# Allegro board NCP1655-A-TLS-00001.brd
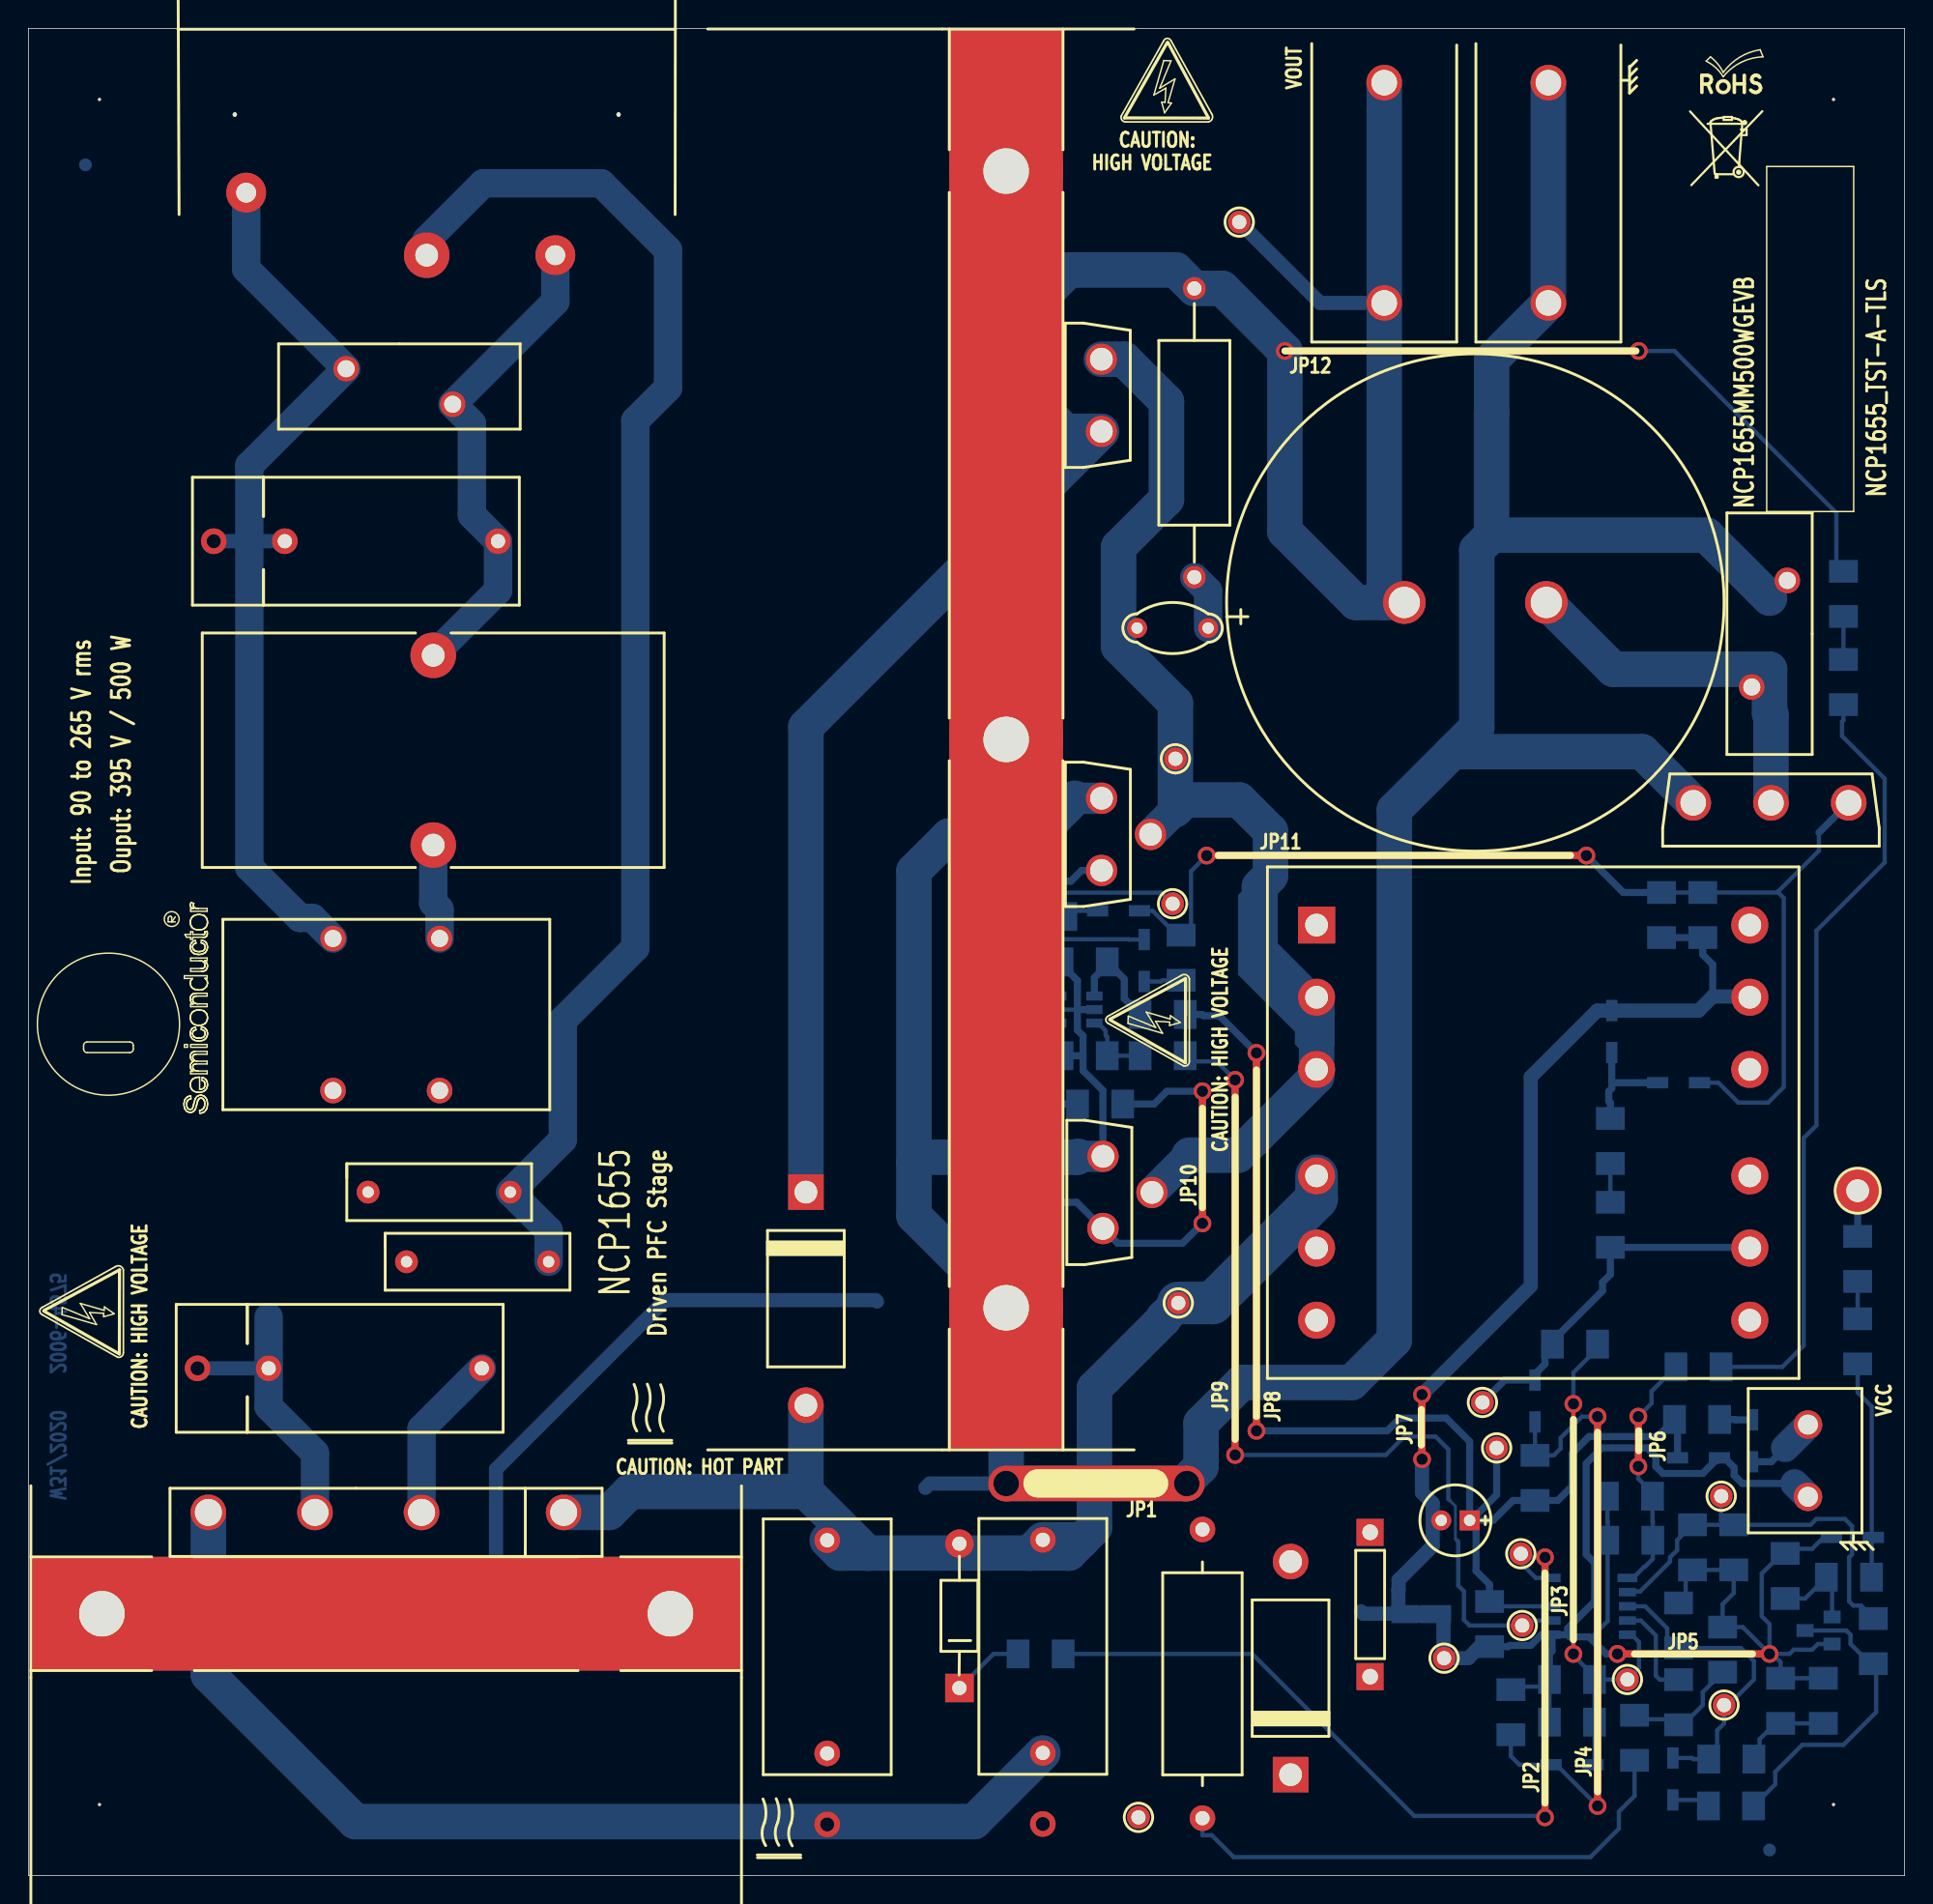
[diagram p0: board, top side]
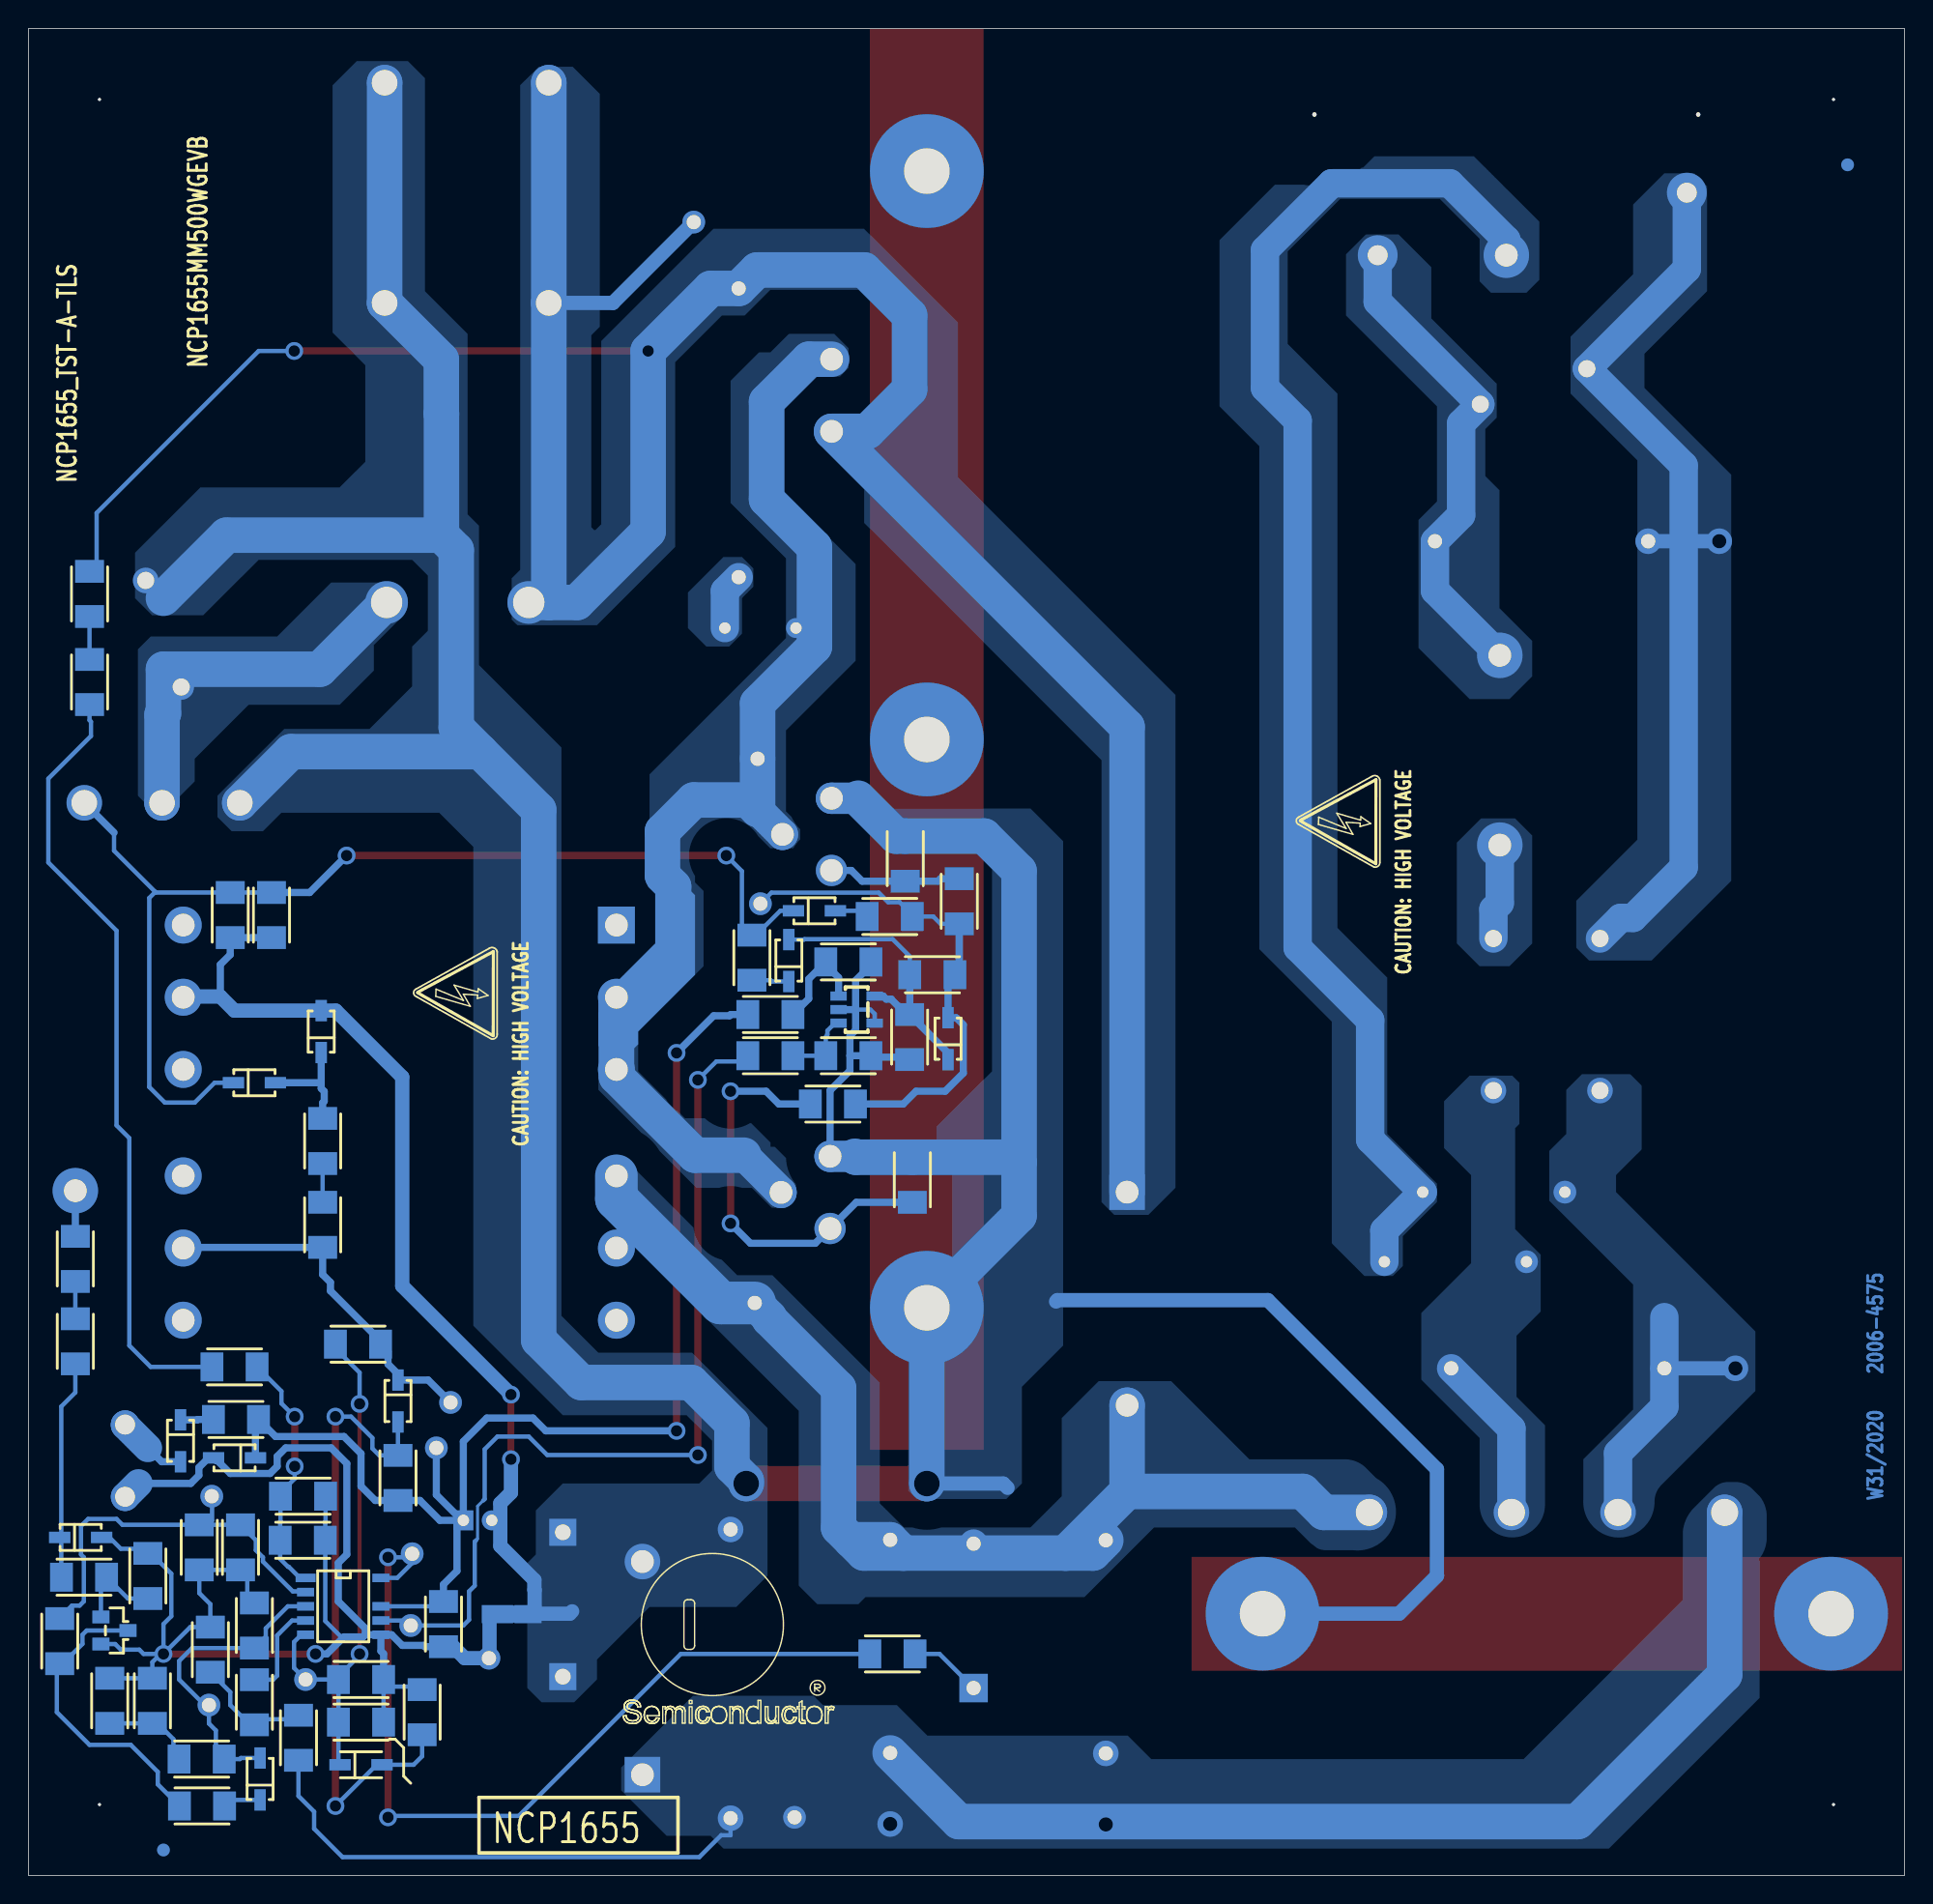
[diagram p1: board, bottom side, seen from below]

Outline 132 x 130 mm; copper layers: TOP, IN1, IN2, BOTTOM. Coordinates in mm from the lower left corner of the outline.
Outline path: 0,130 0,0 132,0 132,130 0,130

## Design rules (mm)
net group DRV: nets CS DRV FB GND N12561389 N12563930 N12564274 N12565260 N12565696 N12574373 N12574975 N12575513 N12577351 N12577403 N12578828 N12578907 N12579145 N12580736 N12597521 N125743211 PFCOK SKIP_CONTROL2 VAUX VCC VM ZCD
net group V_HT: nets VHV

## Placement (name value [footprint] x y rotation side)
C1  470nF/X2  [CAP_E9_L18_H17V5_P15_P20]  25.54 93.91 0 top
C2  470nF/X2  [CAP_E9_L18_H17V5_P15_P20]  24.4 35.7 0 top
C3A  680nF/X2  [CAP_E9_L18_H17V5_P15]  71.37 16.13 270 top
C3B  680nF/X2  [CAP_E9_L18_H17V5_P15]  56.2 16.1 270 top
C4  330uF/450V  [CAPA_CH_D35_H42_P10]  101.8 89.6 0 top
C5  1nF/Y  [CAP_E4_L13_H9_P10]  31.6 43.2 180 top
C6  1nF/Y  [CAP_E4_L13_H9_P10]  28.9 48.1 180 top
C7  220pF  [1206]  74.31 57.7 180 bottom
C8  470nF  [1206]  74.31 64.3 180 bottom
C9  100pF  [CAP_DISK_D5_E3V5_P5]  80.5 87.8 180 top
C10  220pF  [1206]  70 59.01 270 bottom
C11  10nF  [1206]  111.3 51.7 90 bottom
C12  2.2nF  [1206]  117.8 67.6 270 bottom
C14  2.2nF  [1206]  112.7 23.6 180 bottom
C15  10nF  [1206]  119.98 23.1 270 bottom
C16  220pF  [1206]  119.2 15.9 90 bottom
C17  2.2nF  [1206]  116.1 17.6 90 bottom
C18  10nF  [1206]  123.28 12.3 90 bottom
C19  47uF  [CAPA_CH_D5_H11_P2]  100.4 25 180 top
C20  22nF  [1206]  128.7 37.6 270 bottom
C21  22pF  [1206]  104.3 11.5 90 bottom
C22  220nF  [1206]  102.8 17.7 270 bottom
C23  22pF  [1206]  108.6 13.8 180 bottom
CB3  target_cms  [MIRE_LOW]  4.01 120.4 180 bottom
CB4  target_cms  [MIRE_LOW]  122.5 1.8 180 bottom
CM1  2x2mH  [SELF_WE-CMB_M]  25.18 60.6 90 top
D1  FFSPF0865A  [TO220_2P]  75.49 104.18 90 top
D2  1N5406  [DO201AD]  54.7 40.6 270 top
D3  1N5406  [DO201AD]  88.8 14.6 90 top
D4  1N4148  [SOD123]  76.7 67.9 180 bottom
D5  1N4148  [SOD123]  67.3 58.9 90 bottom
D7  1N4148  [SOD123]  116.1 55.8 180 bottom
D8  1N4148  [SOD123]  78.5 64.4 90 bottom
D10  1N4007  [DO41]  65.5 18.28 90 top
D11  1N4148  [SOD123]  106 33.4 270 bottom
D12  1N4148  [SOD123]  115.7 6.8 90 bottom
D13  1N4148  [SOD123]  121.3 30.6 270 bottom
D14  1N4148  [SOD123]  108.6 7.8 180 bottom
DRV  -  [TP]  105.1 17.6 0 top
DZ1  MMSZ18T1  [SOD123]  111.4 59.4 90 bottom
DZ3  MMSZ18T1  [SOD123]  128.32 23.8 180 bottom
DZ4  MMSZ18T1  [SOD123]  117.5 29.4 0 bottom
GND  -  [TP]  99.6 15.3 0 top
HS1  SK481-50  [DISIPATEUR_SK481-50]  25.17 18.43 0 top
HS2  SK481-100  [DISIPATEUR_SK481-100]  68.79 79.96 270 top
ISENSE  -  [TP]  78.1 4.1 0 top
J1  CC_copper  [NONE_CUST]  97.7 18.4 0 bottom
J1A  24.243.2  [CONN_BANANE-4MM_H]  106.94 118.43 90 top
J1B  24.243.1  [CONN_BANANE-4MM_H]  95.39 118.43 90 top
J10  con_3p_1fuse  [CON_SCHUTER_GSF1-1201-31]  28.02 114.04 180 top
J11  HEADER 2  [CON_BORNIER_2_P508]  125.2 29.2 270 top
JGND  STRAP GND  [JUMPER400H]  94.4 14 90 top
L1  175uH  [WE_INDUCTOR_PWD]  105.87 52.99 0 top
L2  56uH  [SELF_2310-V-RC]  28.48 79.2 270 top
NOREF  -  []  5 125 90 top
NOREF#2  -  []  0 130 0 top
NOREF#3  -  []  129.7 123.1 0 top
NOREF#4  -  []  -71.8 6.6 0 top
NOREF#5  -  []  96.1 16.7 0 top
NOREF#6  -  [unnamed#2]  5 125 0 top
NOREF#7  -  [unnamed#2]  127 125 0 top
NOREF#8  -  [unnamed#2]  5 5 0 top
NOREF#9  -  []  0 130 0 top
NOREF#10  -  [unnamed#2]  127 5 0 top
NOREF#11  -  []  -177.26 -15.11 0 top
NOREF#12  -  []  0 0 90 top
NOREF#13  -  []  198 -3.3 180 bottom
NTC1  B57237S0100M0  [DISK_D17_E6_P7-5]  122.5 87.4 270 top
PFCOK  -  [TP]  119.1 26.7 0 top
Q1A  FCFP165N65  [TO220]  75.5 73.28 90 top
Q1B  FCFP165N65  [TO220]  75.6 48.08 90 top
Q2  FCA76N60  [TO247]  122.6 75.5 180 top
Q6  MMBT489LT1  [SOT23]  125.95 17.25 90 bottom
R1  47R  [1206]  111.3 45.8 270 bottom
R2  4.7R  [1206]  81.1 64.6 270 bottom
R3  0R  [RES_1W_AC01]  82.03 101.54 90 top
R4  4.7R  [1206]  68.4 63.4 180 bottom
R5  47R  [1206]  79.8 60.6 180 bottom
R8  4.7R  [1206]  66.51 68.57 270 bottom
R9  4.7R  [1206]  75.4 54.3 180 bottom
R10  27K  [1206]  108.81 37.4 180 bottom
R11  27K  [1206]  70.31 71.57 270 bottom
R12  27K  [1206]  69.81 48.97 270 bottom
R13  27K  [1206]  114.9 67.6 90 bottom
R14  0.03/3W  [RES_LVR03]  82.6 14.2 90 top
R15  47R  [1206]  79.8 57.7 180 bottom
R16  4.7R  [1206]  71.4 67.5 0 bottom
R17  27K  [1206]  71.21 15.6 180 bottom
R18  27K  [1206]  106 27.99 90 bottom
R20  470R  [1206]  129.8 16.5 90 bottom
R21  560k  [1206]  127.7 90.2 270 bottom
R22  1.8M  [1206]  127.7 84 270 bottom
R23  1.8M  [1206]  117.5 35.8 180 bottom
R24  27K  [1206]  112.68 26.7 180 bottom
R25  56K  [1206]  117.08 23.1 90 bottom
R26  1K  [1206]  113 9.7 90 bottom
R27  1K  [1206]  116.1 12.2 90 bottom
R28  1K  [1206]  119.81 8.2 180 bottom
R29  10k  [1206]  126.28 12.3 90 bottom
R30  10k  [1206]  108.6 10.8 0 bottom
R31  47R  [1206]  117.4 32.1 0 bottom
R32  470R  [1206]  119.79 4.9 0 bottom
R33  47R  [1206]  128.7 43.4 270 bottom
R34  10k  [1206]  128.09 21 0 bottom
R35  10k  [1206]  123.6 21.09 90 bottom
SKIP_CTRL2  TP  [TP_T2]  128.7 48.2 0 top
U1  GS1B1580  [PONT_RD_GSI-5S]  25.16 25.56 0 top
U2  NCP1655  [SO10_-1_1MM]  109.85 18.95 180 bottom
U3  FAN3100tsx  [SOT23-5]  73.73 60.95 270 bottom
V1  820513011  [DISK_D17_E6_P7-5]  26.1 104.8 0 top
VAUX  -  [TP]  102.3 33.3 270 top
VCC  -  [TP]  103.3 30.1 270 top
VDS  -  [TP]  80.7 78.6 90 top
VGATE  -  [TP]  80.5 68.4 90 top
VHV  -  [TP]  105 22.65 0 top
VIN  -  [TP]  80.9 40.3 90 top
VM  -  [TP]  119.3 12 0 top
VOUT  -  [TP]  85.19 116.37 0 top
ZCD  -  [TP]  112.5 13.8 0 top

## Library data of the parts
C1 C2 C3A C3B C5-C12 C14-C18 C20-C23 = C
C4 = CAP POL
C19 = C_elect_0
CB3 CB4 = target_cms
CM1 = WE-CMB_0
D1 D4 D5 D7 D8 D10-D14 = MMSD4148T1_0
D2 D3 = D1N4937_1
DRV GND ISENSE PFCOK VAUX VCC VDS VGATE VHV VIN VM VOUT ZCD = SLB4-I/90_0
DZ1 DZ3 DZ4 = zener_sot23_0
HS1 HS2 = Heatsink_KL_196
J1 = CC_cooper
J1A J1B = HEADER 1_1
J10 = con_3p_1fuse
J11 = HEADER 2
JGND = STRAP GND_0
L1 = WE-CMB_1
L2 = L_1
NTC1 = VARISTOR
Q1A Q1B Q2 = SPP11N60S5
Q6 = MMBT2222AL
R1-R5 R8-R18 R20-R35 = R
SKIP_CTRL2 = TEST POINT
U1 = KBUxK_1
U2 = NCL3008x_sup_0
U3 = FAN3100tsx
V1 = VARISTOR SYM

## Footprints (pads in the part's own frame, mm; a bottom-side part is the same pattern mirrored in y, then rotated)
1206
  rect 1.6x2.03 smd: 1(-1.587,0) 2(1.587,0)
CAP_DISK_D5_E3V5_P5
  round 1.4 hole 0.8: 1(-2.5,0) 2(2.5,0)
CAP_E4_L13_H9_P10
  round 1.6 hole 0.8: 1(-5,0) 2(5,0)
CAP_E9_L18_H17V5_P15
  round 1.8 hole 1: 1(7.5,0) 2(-7.5,0)
CAP_E9_L18_H17V5_P15_P20
  round 1.8 hole 1: 1(7.5,0) 2(-7.5,0)
CAPA_CH_D5_H11_P2
  rect 1.4x1.4 hole 0.8: 1(-1,0)
  round 1.4 hole 0.8: 2(1,0)
CAPA_CH_D35_H42_P10
  round 3 hole 2.2: 1(-5,0) 2(5,0)
CON_BORNIER_2_P508
  round 2 hole 1.4: 1(-2.54,0) 2(2.54,0)
CON_SCHUTER_GSF1-1201-31
  round 0.3 hole 6 unplated: (-13.5,-9.9) (13.5,-9.9)
  round 2.8 hole 1.4: 1(12.7,-4.399) 3(-9.05,0)
  round 3.2 hole 1.6: 2(0,0)
CONN_BANANE-4MM_H
  round 2.5 hole 1.8: 1(-7.75,0) 2(7.75,0)
DISIPATEUR_SK481-50
  round 8 hole 3.2: 1(-20,0) 2(20,0)
DISIPATEUR_SK481-100
  round 8 hole 3.2: (0,0) 1(-40,0) 2(40,0)
DISK_D17_E6_P7-5
  round 1.8 hole 1.2: 1(-3.75,1.25) 2(3.75,-1.25)
DO41
  rect 2x2 hole 1: 1(-5.08,0)
  round 2 hole 1: 2(5.08,0)
DO201AD
  rect 2.5x2.5 hole 1.6: 1(-7.5,0)
  round 2.5 hole 1.6: 2(7.5,0)
JUMPER400H
  rect 1.9x1.9 hole 1.1: 1(0,0) 2(10.16,0)
MIRE_LOW
  round 0.9 smd: 1(0,0)
NONE_CUST
  round 0.3 smd: 1(0,0) 2(0.318,0)
PONT_RD_GSI-5S
  round 2.5 hole 1.9: 1(12.5,0) 2(2.5,0) 3(-5,0) 4(-12.5,0)
RES_1W_AC01
  round 1.6 hole 1: 1(-10.16,0) 2(10.16,0)
RES_LVR03
  round 1.8 hole 1: 1(-10.16,0) 2(10.16,0)
SELF_2310-V-RC
  round 3.2 hole 1.6: 1(-6.678,0) 2(6.678,0)
SELF_WE-CMB_M
  round 1.8 hole 1.2: 1(-5.35,3.75) 2(5.35,3.75) 3(5.35,-3.75) 4(-5.35,-3.75)
SO10_-1_1MM
  rect 1.4x0.6 smd: 1(-2.65,2)
  rect 1.2x0.6 smd: 2(-2.65,1) 3(-2.65,0) 4(-2.65,-1) 5(-2.65,-2) 6(2.65,-2) 7(2.65,-1) 8(2.65,0) 10(2.65,2)
SOD123
  rect 1.5x0.8 smd: 1(-1.475,0) 2(1.475,0)
SOT23
  rect 0.9x1.2 smd: 1(0.953,0.953) 2(-0.953,0.953) 3(0,-0.953)
SOT23-5
  rect 0.64x1.15 smd: 1(-0.953,-1.27) 2(0,-1.27) 3(0.953,-1.27) 4(0.953,1.27) 5(-0.953,1.27)
TO220
  round 2.2 hole 1.6: 1(-2.54,0) 2(0,-3.45) 3(2.54,0)
TO220_2P
  round 2.2 hole 1.6: 1(-2.54,0) 2(2.54,0)
TO247
  round 2.5 hole 1.8: 1(-5.47,0) 2(0,0) 3(5.47,0)
TP
  round 1.6 hole 1: 1(0,0)
TP_T2
  round 3.2 hole 1.6: 1(0,0)
unnamed#2
  round 0.2 hole 3 unplated: (0,0)
WE_INDUCTOR_PWD
  rect 2.6x2.6 hole 1.6: (-15.24,13.905)
  round 2.6 hole 1.6: (-15.24,8.825) (-15.24,-8.825) (-15.24,-13.905) (15.24,13.905) (15.24,3.745) (15.24,-3.745) (15.24,-13.905) 3(-15.24,3.745) 4(-15.24,-3.745) 8(15.24,-8.825) 11(15.24,8.825)

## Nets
GND: C14.2 C15.2 C16.2 C17.2 C18.2 C21.2 C22.2 C23.2 DZ3.2(ANODE) DZ4.2(ANODE) GND.1 J1.2 J11.2 Q6.2(EMITTER) R24.2 R25.1 R29.2 R30.1 R35.2 U2.6
PGND: C7.2 C8.2 C10.2 C12.2 C19.2(-) D3.2 DZ1.2(ANODE) HS1.2 HS2.2 J1.1 J1A.1 J1A.2 JGND.1 JGND.2 L1.11 NTC1.1 Q1A.3(S) Q1B.3(S) Q2.3(S) R11.1 R12.1 R13.1 R14.2 U3.2(GND) U3.4(IN-)
VCC: C19.1(+) C22.1 DZ4.1(CATHODE) R5.1 R18.1 R31.1 U2.8 VCC.1
VIN: C3A.2 C3B.2 D2.2 D10.2(A) L1.4 U1.1(+) VIN.1
CS: R27.2 U2.4
DRV: DRV.1 R15.1 U2.7
FB: C14.1 R23.2 R24.1 U2.1
ISENSE: C3A.1 C3B.1 D3.1 ISENSE.1 R14.1 R26.1 U1.4(-)
PFCOK: C15.1 PFCOK.1 R20.2 R25.2 U2.2
SKIP_CONTROL2: R33.1 SKIP_CTRL2.1
VAUX: D11.1(C) L1.8 R1.2 R10.2 VAUX.1
VDS: C9.2 D1.2(A) L1.3 Q1A.2(D) Q1B.2(D) VDS.1
VGATE: D5.2(A) R4.2 R8.2 R9.2 R16.1 VGATE.1
VHV: R17.1 U2.10 VHV.1
VM: C17.1 D12.2(A) R28.2 U2.3 VM.1
VOUT: C4.1 D1.1(C) D2.1 J1B.1 J1B.2 R3.2 R21.1 VOUT.1
ZCD: C23.1 D14.1(C) R10.1 R30.2 U2.5 ZCD.1
N12553072: C1.1 J10.3 L2.1 V1.2
N12553076: C1.2 CM1.2 J10.1 V1.1
N12553080: C5.1 C6.1 J10.2
N12553128: CM1.3 L2.2
N12553139: C2.2 C6.2 CM1.1 U1.3(AC2)
N12553193: C2.1 C5.2 CM1.4 U1.2(AC1)
N12561389: C11.1 R1.1
N12563930: C7.1 R15.2 U3.3(IN+)
N12564274: Q1A.1(G) R8.1 R11.2
N12565260: Q1B.1(G) R9.1 R12.2
N12565625: C4.2 NTC1.2 Q2.2(D)
N12565696: C12.1 D4.1(C) D7.1(C) Q2.1(G) R2.1 R13.2
N12566266: C9.1 R3.1
N12573614: D10.1(C) R17.2
N12574373: R22.2 R23.1
N12574975: C16.1 R26.2 R27.1
N12575513: C18.1 R28.1 R29.1
N12576392: C21.1 D11.2(A) D14.2(A) R18.2
N12577351: D13.1(C) R31.2
N12577403: D13.2(A) J11.1
N12578828: C20.1 R33.2
N12578907: C20.2 DZ3.1(CATHODE) R34.2
N12579145: Q6.1(BASE) R34.1 R35.1
N12580736: D12.1(C) R32.1
N12597521: D4.2(A) R16.2
N12608976: Q6.3(COLLECTOR) R20.1 R32.2
N12614639: C11.2 D7.2(A) DZ1.1(CATHODE)
N12616473: C10.1 D5.1(C) D8.2(A) R4.1 U3.5(OUT)
N12617768: C8.1 R5.2 U3.1(VCC)
N125743211: R21.2 R22.1
N126195281: D8.1(C) R2.2

Pads without a net: CB3 1; CB4 1; HS1 1; HS2 1

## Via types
v1: diameter 1.25, hole 0.8, TOP to BOTTOM, 22 vias
v2: diameter 1.8, hole 1, TOP to BOTTOM, 4 vias
v3: diameter 2.5, hole 1.8, TOP to BOTTOM, 2 vias

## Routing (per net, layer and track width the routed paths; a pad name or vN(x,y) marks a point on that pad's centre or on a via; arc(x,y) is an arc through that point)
GND: length 114.9
  TOP w0.5: v1(111.8,15.6) v1(122.5,15.6)
  BOTTOM w0.3: R30.1 C23.2 106.51,13.3 104.5,13.3 104.3,13.1 C21.2 ; 122.7,15.6 123.28,15.02 C18.2 R29.2 ; 122.7,15.6 v1(122.5,15.6) ; 122.7,15.6 123.9,15.6 124.2,15.9 125.5,15.9 125.89,16.3 126.9,16.3 ; v1(122.5,15.6) 122.5,17.7 121.95,18.25 121.95,21.25 123.38,22.68 123.6,22.68 123.92,23 125.5,23 126.3,23.8 DZ3.2 ; v1(122.5,15.6) 120.61,17.49 C16.2 119.2,19.1 119.98,19.88 C15.2 R25.1 116.9,21.51 116.6,21.21 116.6,19.69 C17.2 ; 109.9,16.7 111.11,17.91 C14.2 111.11,24.91 111.09,24.93 R24.2
  BOTTOM w0.5: 124.26,27.6 120.58,27.6 120.01,28.17 120.01,28.72 119.33,29.4 DZ4.2 118.78,29.2 118.7,29.2 117.8,28.3 115,28.3 114.5,28.8 114.5,29.5 113.9,30.1 110.7,30.1 109.6,29 109.6,22.6 110.2,22 110.2,19.3 108.3,17.4 108.3,16.95 ; v1(111.8,15.6) 111,15.6 109.8,16.8 108.45,16.8 108.3,16.95 ; U2.6 106.45,16.95 105.7,16.2 104.2,16.2 104.11,16.11 C22.2 ; U2.6 107.2,15.8 107.01,15.61 C23.2 ; U2.6 108.3,16.95
  BOTTOM w1: 99.56,18.43 99.56,15.34 GND.1 101.3,15.3 102.11,16.11 C22.2
  BOTTOM w2: 124.26,27.6 J11.2
PGND: length 392.5
  TOP w0.5: v1(98.05,33.85) v1(98.05,29.3)
  TOP w2.5: v3(68.79,27.59) v3(81.5,27.59)
  BOTTOM w0.3: U3.4 72.46,60.65 72.76,60.95 73.8,60.95 ; L1.11 121.11,61.87
  BOTTOM w0.5: 118.5,61.87 118.5,64.11 117.8,64.81 C12.2 R13.1 ; 70,57.42 70.17,57.6 72.62,57.6 C7.2 74.2,57.7 ; 73.8,60.95 73.8,63 72.72,64.08 C8.2 ; 73.8,60.95 U3.2 ; 73.8,60.95 73.8,59.5 74.2,59.1 74.2,57.7 ; 74.2,57.7 74.2,56.65 75.6,55.25 Q1B.3
  BOTTOM w1: 63.11,27.29 63.41,27.59 v3(68.79,27.59) ; 59.7,40.4 59.6,40.5 44.8,40.5 32.9,28.6 32.9,21.1 35.57,18.43 HS1.2 ; C19.2 99.3,24.9 98.8,24.9 ; v1(98.05,33.85) 105.7,41.5 105.7,56.2 110.38,60.88 DZ1.2 117.51,60.88 118.5,61.87 121.11,61.87 ; 98.8,24.9 98.8,23.2 96.4,20.8 96.4,20.11 96.38,20.09 96.38,18.43 93.91,18.43 93.74,18.6 ; 98.8,24.9 98.8,26.2 98.05,26.95 v1(98.05,29.3)
  BOTTOM w2.2: Q1A.3 73.62,75.82 ; Q1B.3 73.85,50.62
  BOTTOM w2.5: 100.2,79.1 96.1,75 96.1,37.7 93.1,34.7 85.36,34.7 82.5,31.84 82.5,28.79 81.5,27.79 v3(81.5,27.59) ; 100.2,79.1 101.9,80.8 101.9,93.3 102.94,94.34 ; 100.2,79.1 113.53,79.1 Q2.3 ; 73.85,50.62 73.79,50.56 R12.1 62.66,50.56 62.3,50.2 ; 62.3,50.2 62.3,70.7 64.76,73.16 R11.1 70.96,73.16 73.62,75.82 ; 62.3,50.2 62.3,46.45 HS2.2 v3(68.79,27.59) ; 102.94,94.34 118.06,94.34 122.5,89.9 ; 102.94,94.34 102.94,102.89 102.95,102.9 102.95,106.69 J1A.1 J1A.2
VCC: length 92.2
  TOP w0.5: v1(86.4,31.3) v1(86.4,57.9)
  BOTTOM w0.3: 115.8,32.09 R31.1 ; U2.8 103.14,18.95 C22.1
  BOTTOM w0.5: 101.85,25 C19.1 101.4,30.55 99.75,32.2 96.5,32.2 95.6,31.3 v1(86.4,31.3) ; 101.85,25 101.85,21.44 102.8,20.49 C22.1 ; 101.85,25 103.05,25 104.45,26.4 R18.1 107.6,26.4 108.6,27.4 108.6,29.7 109.8,30.9 114.61,30.9 115.8,32.09 116.03,31.86 DZ4.1 ; 101.85,25 101.85,25.35 103.3,26.8 VCC.1 ; R5.1 82.59,60.6 82.67,60.51 83.79,60.51 v1(86.4,57.9)
VIN: length 86.5
  BOTTOM w2.5: 74.1,23.59 75,24.48 75,34.3 79.87,39.17 79.87,39.27 VIN.1 ; 74.1,23.59 73.22,22.7 70.44,22.7 ; 74.1,23.59 74.06,23.63 C3A.2 70.44,22.7 ; 59.03,22.7 57.1,22.7 C3B.2 ; 59.03,22.7 70.44,22.7 ; 59.03,22.7 54.7,27.03 ; 54.7,27.03 D2.2 ; 54.7,27.03 42.33,27.03 40.86,25.56 U1.1
  BOTTOM w3: 90.63,49.24 90.63,47.63 83.3,40.3 VIN.1
CS: length 7
  BOTTOM w0.3: R27.2 114.78,13.79 114.5,14.07 114.5,16.9 113.45,17.95 U2.4
DRV: length 65.5
  TOP w0.5: v1(84.9,56) v1(84.9,29.6)
  BOTTOM w0.2: 100,26.4 100.4,26 100.4,23.7 100.5,23.6
  BOTTOM w0.3: v1(84.9,29.6) 95.5,29.6 96.8,30.9 99,30.9 99.9,30 99.9,26.5 100,26.4 ; R15.1 81.5,57.7 81.9,57.3 83.6,57.3 v1(84.9,56) ; U2.7 105.45,17.95 DRV.1 101.4,17.6 101,18 101,20 100.6,20.4 100.6,23.5 100.5,23.6
FB: length 17.4
  TOP w0.5: v1(113.27,32.3) v1(113.27,28.8)
  BOTTOM w0.3: R23.2 114.2,34.09 114.2,33.23 v1(113.27,32.3) ; U2.1 112.9,20.95 113.69,21.74 113.74,21.74 114.29,22.29 C14.1 114.29,24.91 114.27,24.93 R24.1 114.27,26.93 113.27,27.93 v1(113.27,28.8)
ISENSE: length 113.7
  BOTTOM w0.3: 71.4,8.6 C3A.1 ; R26.1 113,5.6 111.9,4.5 111.9,3.3 109.9,1.3 84.8,1.3 83.26,2.84 82.6,2.84 R14.1
  BOTTOM w2.5: U1.4 12.66,14.14 23,3.8 66.54,3.8 C3A.1
  vias: v2(56.2,3.6) v2(71.37,3.63)
PFCOK: length 28.6
  BOTTOM w0.3: U2.2 112.55,20 113.4,20 115.5,22.1 115.5,22.4 116,22.9 116,23.61 R25.2 119.38,24.69 ; 119.38,24.69 119.08,24.99 119.08,26.68 PFCOK.1 ; 119.38,24.69 C15.1 125.39,24.69 125.8,25.1 127.8,25.1 128.3,24.6 128.3,22.6 128.1,22.4 128.1,19.3 128.4,19 128.94,19 129.85,18.09 R20.2
SKIP_CONTROL2: length 3.2
  BOTTOM w0.5: SKIP_CTRL2.1 R33.1
VAUX: length 25.7
  BOTTOM w0.3: 105.98,34.88 D11.1
  BOTTOM w0.5: VAUX.1 103.88,34.88 105.98,34.88 105.98,35.27 106.7,36 106.7,36.88 R10.2 107.22,37.62 110.75,41.15 110.75,41.75 111.3,42.3 R1.2 121.06,44.21 121.11,44.16
VDS: length 82.1
  BOTTOM w2.2: 81.67,50.7 Q1B.2 ; 80.7,75.03 Q1A.2
  BOTTOM w2.5: 81.67,50.7 85.1,50.7 90.63,56.23 L1.3 90.63,60.57 86.61,64.59 86.61,69.61 87.39,70.39 87.39,73.5 85.19,75.7 81.37,75.7 80.7,75.03 VDS.1 80.7,82.5 76.7,86.5 76.7,93.5 80.07,96.87 80.07,103.73 77.08,106.72 D1.2
VGATE: length 35.4
  BOTTOM w0.3: VGATE.1 79.72,69.18 72.18,69.18 71.5,68.5 70.7,68.5 69.81,67.61 R16.1 68.34,67.5 67.83,66.98 R8.2
  BOTTOM w0.5: R8.2 66.51,64.3 66.81,64 R4.2 67.3,62.91 D5.2 66.72,60.38 66.22,59.88 66.22,56.48 67.5,55.2 69.55,55.2 70.45,54.3 R9.2
VHV: length 62.1
  TOP w0.5: v1(106.7,22.4) v1(106.7,4.1)
  BOTTOM w0.3: v1(106.7,22.4) 105.25,22.4 VHV.1 105,22 106.05,20.95 U2.10 ; R17.1 86.1,15.6 97.5,4.2 106.6,4.2 v1(106.7,4.1)
VM: length 21.8
  BOTTOM w0.3: D12.2 117.05,8.28 117.12,8.2 R28.2 118.22,8.6 118.81,9.19 118.81,10.21 119.3,10.7 VM.1 119.6,12 121.4,13.8 121.4,15.1 120.49,16.01 C17.1 115.3,16.81 115.3,17.4 113.75,18.95 U2.3
VOUT: length 216.4
  TOP w0.5: v1(113.3,107.3) v1(88.4,107.3)
  BOTTOM w0.3: R21.1 127.6,91.79 127.2,92.19 127.2,95.9 115.8,107.3 v1(113.3,107.3)
  BOTTOM w1: VOUT.1 90.88,110.68 J1B.1
  BOTTOM w2.5: D2.1 54.7,80.85 D1.1 72.96,101.64 70,104.6 70,109.8 73.2,113 80.73,113 R3.2 84,111.7 v1(88.4,107.3) 88.4,94.6 93.4,89.6 95.39,89.6 ; C4.1 95.39,89.6 ; 95.39,89.6 J1B.1 J1B.2
ZCD: length 37.5
  TOP w0.3: v1(108.7,15.6) v1(108.7,33.2)
  BOTTOM w0.3: 110.47,13.8 110.19,13.52 R30.2 110.19,7.8 110.08,7.8 ; 110.47,13.8 C23.1 110.19,14.01 108.7,15.5 v1(108.7,15.6) ; 110.47,13.8 ZCD.1 113.31,14.61 113.31,16.44 112.8,16.95 U2.5 ; v1(108.7,33.2) 108.7,35.4 110.4,37.1 R10.1
N12553072: length 34.4
  BOTTOM w2: J10.3 37.07,110.77 V1.2 31.2,102.2 31.2,95.75 C1.1 33.04,90.44 L2.1
N12553076: length 66.2
  BOTTOM w1: C1.2 v2(13.04,93.91)
  BOTTOM w2: CM1.2 19.98,67.4 19.1,67.4 15.54,70.96 15.54,99.24 V1.1 15.32,113.08 J10.1
N12553080: length 98.6
  BOTTOM w2: C5.1 36.6,45.4 C6.1 37.6,51.8 37.6,60.2 42.7,65.3 42.7,102.4 45,104.7 45,114.4 40.3,119.1 32,119.1 28.02,115.12 J10.2
N12553128: length 6.8
  BOTTOM w2: L2.2 28.48,68.45 28.93,68 CM1.3
N12553139: length 20.1
  BOTTOM w1: C2.2 v2(11.9,35.7)
  BOTTOM w2: U1.3 20.16,29.74 16.9,33 C2.2 16.9,39.3
N12553193: length 11.9
  BOTTOM w2: U1.2 27.66,31.46 C2.1
N12561389: length 2.7
  BOTTOM w0.3: C11.1 R1.1
N12563930: length 5.1
  BOTTOM w0.3: U3.3 75.25,59.99 75.79,59.46 75.79,59.21 75.8,59.2 75.8,59.12 75.9,59.02 C7.1 R15.2
N12564274: length 9.4
  BOTTOM w0.5: R8.1 67.83,70.16 68,69.98 R11.2 73.34,69.98 74.1,70.74 Q1A.1
N12565260: length 29.8
  TOP w0.5: v1(82.6,55.2) v1(82.6,45.9)
  BOTTOM w0.5: v1(82.6,55.2) 80.1,55.2 79.2,54.3 R9.1 ; v1(82.6,45.9) 81.2,44.5 76.64,44.5 Q1B.1 73.76,47.38 R12.2
N12565625: length 27.1
  BOTTOM w2.5: Q2.2 122.6,81.7 122.5,81.8 122.5,84.9 111.5,84.9 C4.2
N12565696: length 80.7
  TOP w0.5: v1(109.61,71.79) v1(82.9,71.79)
  BOTTOM w0.3: 123.07,69.23 123.03,69.19 C12.1 R13.2 ; 123.07,69.23 123.5,68.8 123.5,55.5 122.4,54.4 120.3,54.4 118.9,55.8 117.58,55.8 ; 123.07,69.23 125.98,72.13 125.98,73.41 ; v1(82.9,71.79) 81.8,70.69 81.8,66.5 81.49,66.19 R2.1 80.81,66.19 79.1,67.9 D4.1
  BOTTOM w0.5: R13.2 112.21,69.19 v1(109.61,71.79) ; Q2.1 125.98,73.41
N12566266: length 4
  BOTTOM w2: C9.1 83,90.41 R3.1
N12573614: length 5.1
  BOTTOM w0.3: D10.1 67.9,15.6 R17.2
N12574373: length 55.2
  BOTTOM w0.3: R22.2 127.7,81.31 127.6,81.21 127.6,80.2 130.6,77.2 130.6,71.3 125.8,66.5 125.8,52.8 124.9,51.9 124.9,37.3 123.4,35.8 R23.1
N12574975: length 8.6
  BOTTOM w0.3: 116.12,10.61 R27.1 ; 116.12,10.61 116.41,10.61 117.8,12 117.8,12.91 C16.1 ; 116.12,10.61 115.73,11 113.29,11 R26.2
N12575513: length 6.5
  BOTTOM w0.3: R29.1 C18.1 122.91,10.71 121.8,9.6 121.8,8.6 R28.1
N12576392: length 44.8
  TOP w0.5: v1(110.4,4.9) v1(110.4,32.3)
  BOTTOM w0.3: v1(110.4,32.3) 109.3,32.3 107.8,30.8 107.8,30.06 107.31,29.57 R18.2 D11.2 ; v1(110.4,4.9) 107.5,7.8 D14.2 104.9,7.8 104.3,8.4 C21.1
N12577351: length 2.3
  BOTTOM w0.5: R31.2 120.09,32.1 120.11,32.08 D13.1
N12577403: length 5
  BOTTOM w0.5: D13.2 122.62,29.12 123.6,30.1
  BOTTOM w2: 123.6,30.1 125.2,31.7 J11.1
N12578828: length 2.6
  BOTTOM w0.3: C20.1 R33.2
N12578907: length 15.6
  BOTTOM w0.3: C20.2 128.7,34 129.69,33.01 129.69,23.69 ; 129.69,23.69 DZ3.1 ; 129.69,23.69 129.69,21 R34.2
N12579145: length 6.5
  BOTTOM w0.3: R35.1 125,19.5 R34.1 126.9,20.6 Q6.1
N12580736: length 2.7
  BOTTOM w0.3: D12.1 117.9,5.33 118.2,5.03 R32.1
N12597521: length 2.5
  BOTTOM w0.3: 75.22,67.9 73.29,67.9 72.99,67.6 R16.2
N12608976: length 21.6
  BOTTOM w0.3: R32.2 122.9,6.42 122.9,7.3 124.8,9.2 127.7,9.2 130,11.5 130,14.71 R20.1 129.8,15.1 129.5,15.4 129.1,15.4 128.2,16.3 128.2,16.95 127.9,17.25 Q6.3
N12614639: length 8
  BOTTOM w0.5: C11.2 111.3,54.39 111.19,54.5 111.19,55.19 111.4,55.4 111.4,55.9 ; 111.4,55.9 111.5,55.8 D7.2 ; 111.4,55.9 DZ1.1
N12616473: length 20.4
  BOTTOM w0.3: R4.1 69.99,64.69 71.2,65.9 77.4,65.9 77.42,65.88 D8.2
  BOTTOM w0.5: D5.1 67.3,57.9 C10.1 ; U3.5 71.86,61.9 71.64,61.68 71.3,61.68 70.22,60.6 C10.1 ; C10.1 69.99,60.61 R4.1
N12617768: length 7.4
  BOTTOM w0.5: U3.1 75,63.2 75.9,64.1 C8.1 77.1,63.1 77.1,61.71 R5.2
N125743211: length 3
  BOTTOM w0.3: R22.1 R21.2
N126195281: length 2.6
  BOTTOM w0.3: R2.2 79.78,63.01 79.7,62.92 78.5,62.92

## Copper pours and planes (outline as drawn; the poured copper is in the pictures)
GND on BOTTOM (solid shape): 100.1,17.77 97.9,17.77 97.9,19.04 100.1,19.04
PGND on TOP (solid shape): 72.79,29.96 64.79,29.96 64.79,129.96 72.79,129.96
PGND on BOTTOM (solid shape): 97.8,17.77 95.9,17.77 95.9,19.04 97.8,19.04
PGND on BOTTOM: 69.5,26.5 63.2,26.5 62.1,27.6 62.1,34.4 59.2,37.3 59.2,72.8 61.5,75.1 72.1,75.1 72.1,73.6 70.8,72.3 65.5,72.3 64.2,71 64.2,56.6 68.1,52.7 68.1,50 68,49.9 67,49.9 67,42.7 70.1,39.6 70.1,27.1
PGND on BOTTOM: 82.2,18.9 80,21.1 80,31.5 85.3,36.8 91.9,36.8 94.5,39.4 94.5,79.4 100.3,85.2 100.3,95 101.1,95.8 101.1,108.5 104.1,111.5 104.1,126.5 105.3,127.7 108.9,127.7 110.6,126 110.6,108.6 108.3,106.3 108.3,99.5 110.1,97.7 119.9,97.7 124.5,93.1 124.5,89.9 123.3,88.7 119.7,88.7 115.8,92.6 105,92.6 103.9,91.5 103.9,87.6 105,86.5 105,83.7 108,80.7 114,80.7 118.7,76 118.7,74.5 117.7,73.5 115.5,73.5 114.2,74.8 103.1,74.8 100.7,72.4 100.7,38.7 94.4,32.4 85.7,32.4 83.9,30.6 83.9,28.5 84.8,27.6 94.4,27.6 96.3,25.7 96.3,22.6 96.9,22 96.9,13.2 95.9,12.2 93.6,12.2 92,13.8 92,15.2 88.3,18.9
VIN on BOTTOM: 57.7,19.6 52.8,24.5 42.9,24.5 41.7,23.3 41.24,23 40.7,22.9 38.8,22.9 35.91,24.77 37.17,27.97 37.9,28.7 38.59,29.14 39.4,29.3 46.1,29.3 51.6,34.8 56.7,34.8 59.3,32.2 59.3,26.7 61.5,24.5 70.4,24.5 72.1,26.2 72.1,34.7 80.5,43.1 82.7,43.1 90,50.4 91,50.4 91.9,49.5 91.9,46.8 77.8,32.7 77.8,20.4 76.5,19.1 73.6,19.1 73.1,19.6
ISENSE on BOTTOM: 13.36,27.34 12.91,27.61 12.4,27.7 11.8,27.7 11.2,27.55 10.7,27.2 10.2,26.7 9.83,26.04 9.7,25.3 9.7,23.69 9.9,22.83 10.4,22.1 10.2,22.3 10.2,12.5 20.8,1.9 83.1,1.9 84,2.8 87.1,2.8 90.3,6 90.3,7.6 85.25,12.65 76.75,12.65 76.1,12 70.9,12 68.75,9.85 54.65,9.85 53,8.2 26.8,8.2 15.6,19.4 15.6,24.2 15.35,25.12 14.8,25.9
Net_15 on IN2: 0,0 0,130 132,130 132,0
Net_57 on TOP (solid shape): 50.17,14.43 0.17,14.43 0.17,22.43 50.17,22.43
VDS on BOTTOM (solid shape): 88.4,70.6 88.4,69.6 87.9,69.1 87.9,65.6 91.9,61.6 91.9,58.4 91.5,58 89.6,58 89.1,58.5 89.1,59.4 85.1,63.4 85.1,69 86.8,70.7 88.3,70.7
VDS on BOTTOM: 76.5,105.5 74.9,105.5 74.3,106.1 74.3,107.5 75.3,108.5 78.5,108.5 79.8,107.2 80.6,107.2 82.6,105.2 82.6,96.6 78.7,92.7 78.7,87.1 88.3,77.5 88.3,65.2 91.9,61.6 91.9,55.3 85,48.4 81.1,48.4 79.7,47 78.7,47 78,47.7 78,49.8 81.5,53.3 85.8,53.3 89.1,56.6 89.1,59.4 84.5,64 84.5,69.3 85.1,69.9 85.1,72.8 84.1,73.8 81.3,73.8 79.8,72.3 78.1,72.3 77.7,72.7 77.7,73.9 78.7,74.9 78.7,80.6 73.8,85.5 73.8,92.3 78.8,97.3 78.8,103.2
VOUT on BOTTOM: 53.2,46.5 55.6,46.5 56.5,47.4 56.5,78.5 73.2,95.2 73.2,97.9 76.3,101 76.3,102.1 75.6,102.8 73.4,102.8 71.2,105 71.2,109.2 73.6,111.6 79.8,111.6 81.6,109.8 83.2,109.8 86.5,106.5 86.5,93.5 92,88 97.6,88 98,88.4 98,91.3 97.4,91.9 97.4,126 96.1,127.3 93.7,127.3 91.8,125.4 91.8,109 92.4,108.4 92.4,94.9 92.2,94.7 92.1,94.7 91.7,95.1 91.7,108 83.8,115.9 73.2,115.9 66.6,109.3 66.6,98.4 51.3,83.1 51.3,48.4
N12553072 on BOTTOM: 37.9,115.5 35.6,115.5 33.3,113.2 33.3,109.6 28.7,105 28.7,102.6 29.5,101.8 29.5,98.5 28.5,97.5 28.5,89.2 26.2,86.9 26.2,84.4 27.8,82.8 30.6,82.8 34.2,86.4 34.2,95.4 32.9,96.7 32.9,103.4 39.3,109.8 39.3,114.1
N12553076 on BOTTOM: 13.9,118.9 13.9,111.5 18.3,107.1 18.3,104.7 12.2,98.6 12.2,70 17.8,64.4 22.2,64.4 23.1,65.3 23.1,68.6 18.8,72.9 18.8,99.6 23.5,104.3 23.5,108.3 19.1,112.7 19.1,117.6 16.9,119.8 14.8,119.8
N12553080 on BOTTOM: 25.7,116.4 25.7,112.3 26.6,111.4 29.1,111.4 29.9,112.2 29.9,115.2 32.7,118 39.7,118 43.4,114.3 43.4,107.8 39.9,104.3 39.9,66.7 36.4,63.2 36.4,52.2 32.9,48.7 32.9,47.4 35.3,45 35.3,42.9 36,42.2 38,42.2 40.3,44.5 40.3,60.1 45.4,65.2 45.4,100.6 48.2,103.4 48.2,115.1 44.3,119 41.9,119 40.7,120.2 38.1,120.2 37.3,121 30.3,121
N12553128 on BOTTOM: 29.8,74.4 27.4,74.4 26.2,73.2 26.2,65.6 27.8,64 29.9,64 31.5,65.6 31.5,72.7
N12553139 on BOTTOM: 22.6,26.5 20.19,23.79 17.59,26.31 17.46,26.96 17.1,27.5 10.5,34.1 10.5,38.3 20.3,48.1 20.3,49.3 18.5,51.1 18.5,55.6 19.3,56.4 22.7,56.4 23.8,55.3 23.8,52.2 25,51 25,47.5 19.1,41.6 19.1,32.8 22.6,29.3
N12553193 on BOTTOM: 29.9,26 27.6,23.8 25.3,26 25.3,26 25.3,31.7 27.3,33.7 27.3,38 25.6,39.7 25.6,43.7 27.4,45.5 27.4,52.6 27.1,52.9 27.1,55.8 27.6,56.3 30.6,56.3 32.4,54.5 32.4,51.2 30.5,49.3 30.5,43.1 34,39.6 34,34.9 29.9,30.8 29.9,26
N12565625 on BOTTOM: 107.2,91 110.7,91 114.5,87.2 123.4,87.2 124.3,86.3 124.3,76 122.8,74.5 120.3,77 120.3,78.6 116.5,82.4 110.1,82.4 107.7,84.8 107.7,86.6 105.8,88.5 105.8,89.6
N12566266 on BOTTOM: 83.1,92.8 81.8,92.8 81,92 81,90.7 81.8,89.9 81.8,87.4 82.7,86.5 84.3,86.5 85.6,87.8 85.6,90.3

Small or netless copper shapes (teardrops, artwork), in the pictures only: 1 on BOTTOM

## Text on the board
BOTTOM: BOT 1/2 | 2006-4575 | W31/2020
Ref Des/Silkscreen Bottom: SILK_BOT | CAUTION: HIGH VOLTAGE | NCP1655MM500WGEVB | NCP1655_TST-A-TLS | NCP1655
User.Comments: VE_BOT | VE_TOP
TOP: TOP 2/2
Ref Des/Assembly Top: VOUT | GND | VCC
Ref Des/Silkscreen Top: CAUTION: HOT PART | HIGH VOLTAGE | CAUTION: | JP1 | JP11 | JP12 | JP5 | CAUTION: HIGH VOLTAGE | JP10 | JP9 | JP8 | VOUT | JP7 | JP2 | JP3 | JP4 | JP6 | VCC | Input: 90 to 265 V rms | Ouput: 395 V / 500 W | NCP1655MM500WGEVB | NCP1655_TST-A-TLS | SILK_TOP | Driven PFC Stage | NCP1655
IN1: IN1 3/4
IN2: IN2 2/4
DIMENSION: JP1 | JP11 | JP12 | JP5 | JP10 | JP9 | JP8 | JP7 | JP2 | JP3 | JP4 | JP6 | isolated single straded wire  AWG26(x11) | isolated single straded wire  AWG15(x1) 0.5' pitch | A
ASSEMBLY_BOTTOM: A
User.5: CHEMICAL NiAu | 70um(2oz) | THICKNESS | MATERIAL | STACKUP | FINISH | SILKSCREEN | MINIMAL GAP | MINIMAL SLIVER | BOARD THICKNESS | SOLDER MASK | COPPER THICKNESS | MARKED ON BOTTOM SOLDERMASK | ALL BOARD ELECTRICALLY TESTED | MANUFACTURE 'S LOGO & DATECODE | COMPLIANT RoHS DIRECTIVE 2011/65/UE | SF /1LAYER | WHITE TOP&BOT | FR4 IMPROVED (low CTE) | GREEN BOT | 200um /8mils | 1.6mm /63mils | A | SPEC:
User.6: NCP1655-A-TLS-0001 2006-4575   W31/2020
User.7: FIGURE | SIZE | 0.8 | 1.0 | 1.1 | 1.2 | 1.4 | 1.6 | 1.8 | 1.9 | 2.2 | 3.2 | 3.0 | 6.0 | DRILL CHART: TOP to BOTTOM | ALL UNITS ARE IN MILLIMETERS | PLATED | NON-PLATED | QTY | 30 | 31 | 2 | 8 | 4 | 24 | 9 | 5
